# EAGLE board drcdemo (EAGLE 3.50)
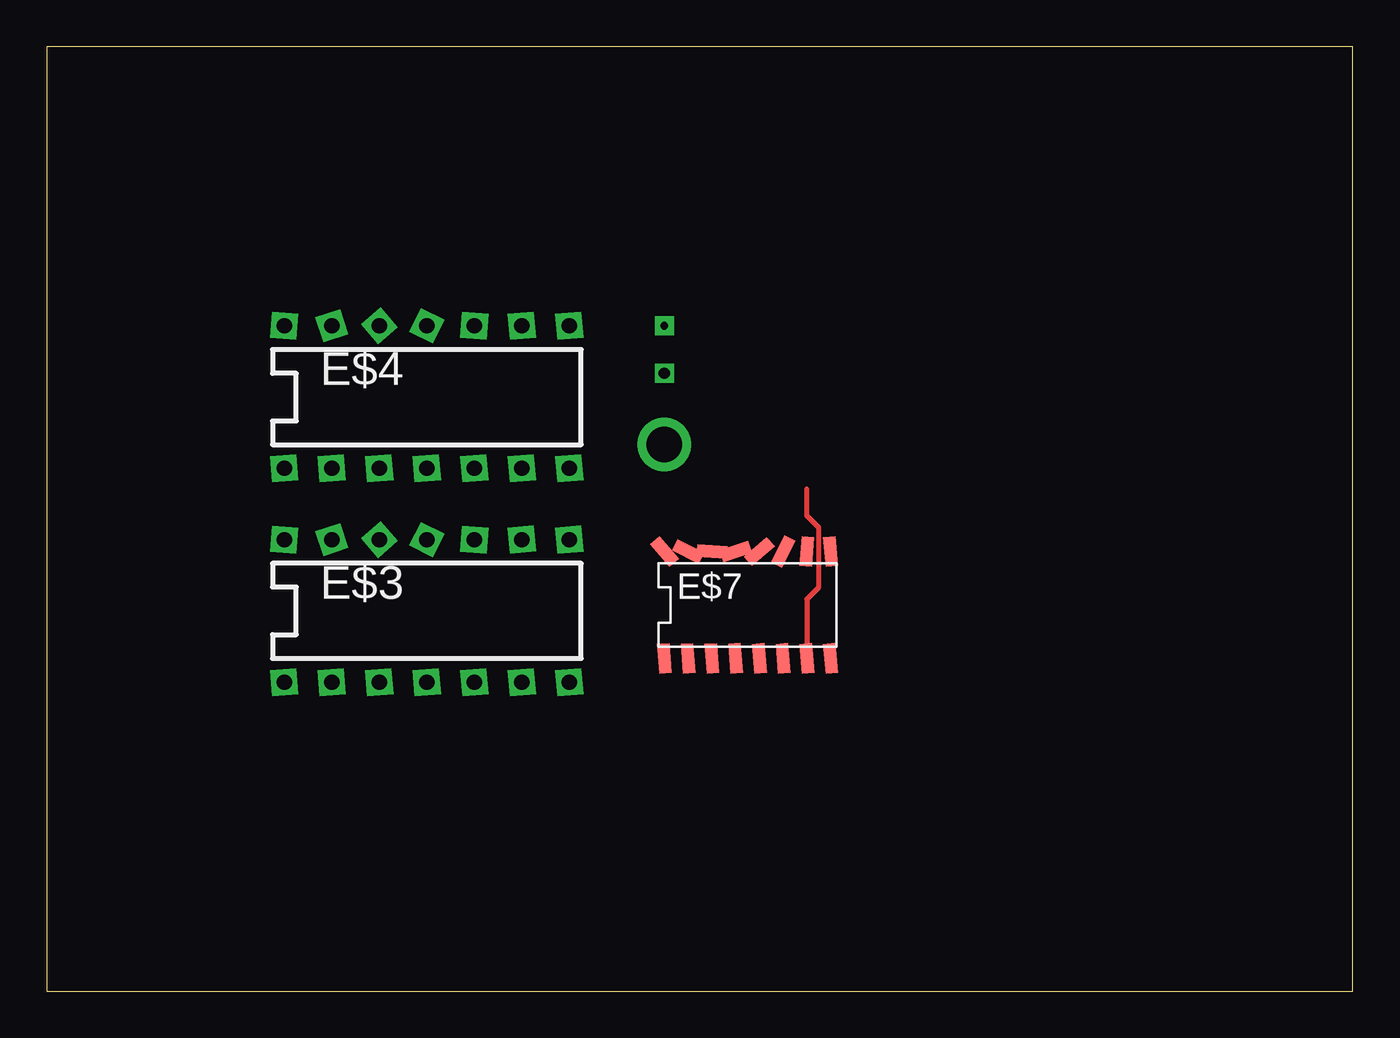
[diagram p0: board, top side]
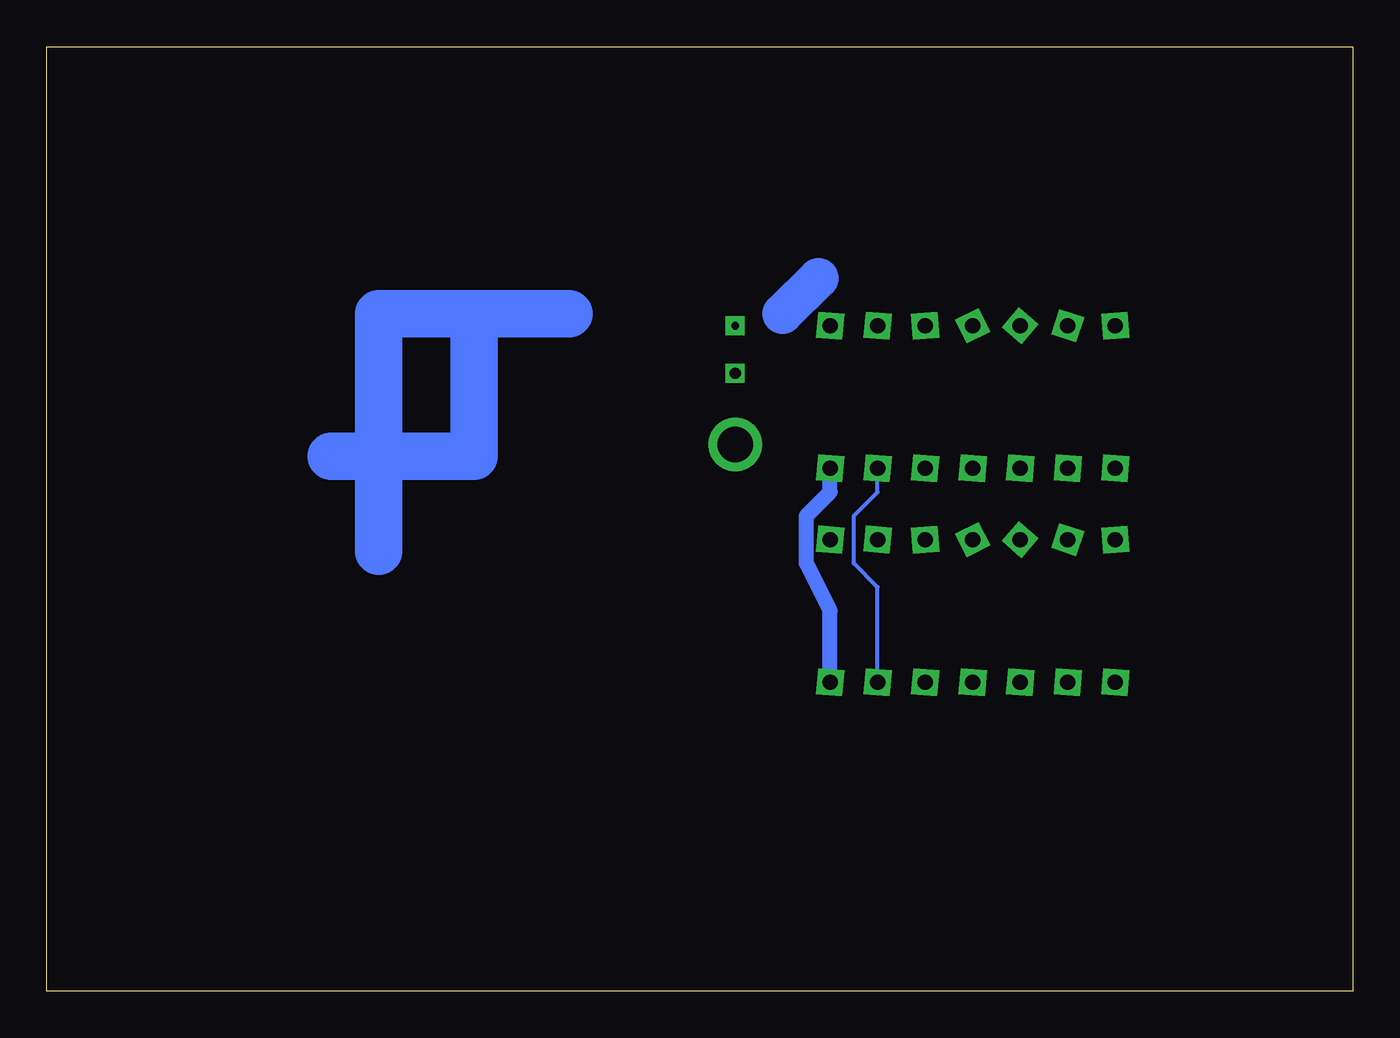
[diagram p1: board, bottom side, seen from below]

Size 69.82 x 50.47 mm. Coordinates in mm from the lower left corner, seen from the top.
Outline: 0,0 69.83,0 69.83,50.47 0,50.47 0,0
Copper layers used: Top, Bottom

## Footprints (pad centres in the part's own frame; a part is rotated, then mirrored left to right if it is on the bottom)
L14 = drill 0.813 pad 1.397 square:  0,0;  2.54,0;  5.08,0;  7.62,0;  10.16,0;  12.7,0;  15.24,0;  15.24,7.62;  12.7,7.62;  10.16,7.62;  7.62,7.62;  5.08,7.62;  2.54,7.62;  0,7.62
16 = smd 0.66 x 1.6 rotated 4.3:  0,0;  7.62,5.715 | smd 0.66 x 1.6 rotated 139.3:  0,5.715 | smd 0.66 x 1.6 rotated 4.4:  1.27,0 | smd 0.66 x 1.6 rotated 4.5:  2.54,0 | smd 0.66 x 1.6 rotated 116.8:  1.27,5.715 | smd 0.66 x 1.6 rotated 94.3:  2.54,5.715 | smd 0.66 x 1.6 rotated 4.6:  3.81,0 | smd 0.66 x 1.6 rotated 71.8:  3.81,5.715 | smd 0.66 x 1.6 rotated 4.7:  5.08,0;  6.35,0 | smd 0.66 x 1.6 rotated 49.3:  5.08,5.715 | smd 0.66 x 1.6 rotated 26.8:  6.35,5.715 | smd 0.66 x 1.6 rotated 4.8:  7.62,0 | smd 0.66 x 1.6 rotated 4.9:  8.89,0 | smd 0.66 x 1.6 rotated 5:  8.89,5.715

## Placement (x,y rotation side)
E$3  [L14]  12.7,16.51 0 top
E$4  [L14]  12.7,27.94 0 top
E$7  [16]  33.02,17.78 0 top

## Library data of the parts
E$3 E$4 = EAGLE
E$7 = SMD

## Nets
S$1: E$3. E$4.
S$3: E$3. E$4.
S$6: E$7.

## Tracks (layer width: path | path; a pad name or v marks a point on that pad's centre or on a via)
S$1
  Bottom 0.813: 27.94,16.51 27.94,20.32 29.21,22.86 29.21,25.4 27.94,26.67 27.94,27.94
S$2  (via drill 0.41 pad 1.02)
  other vias: 33.02,35.56
S$3
  Bottom 0.203: 25.4,16.51 25.4,21.59 26.67,22.86 26.67,25.4 25.4,26.67 25.4,27.94
S$4  (via drill 0.61 pad 0.76)
  other vias: 33.02,33.02
S$5  (via drill 1.91 pad 2.16)
  other vias: 33.02,29.21
S$6
  Top 0.254: 40.64,26.82 40.64,25.4 41.27,24.77 41.27,21.59 40.64,20.95 40.64,17.78
S$7
  Bottom 2.54: 46.99,35.56 46.99,28.57 54.61,28.57
S$8
  Bottom 2.54: 41.91,36.2 52.07,36.2 52.07,23.5
S$9
  Bottom 2.159: 28.57,38.1 30.48,36.2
